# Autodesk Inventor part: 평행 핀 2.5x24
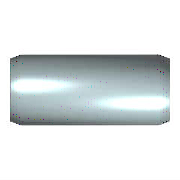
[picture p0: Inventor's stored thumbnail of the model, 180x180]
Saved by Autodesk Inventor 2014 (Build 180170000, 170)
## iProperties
Created: 2012-02
Part Number: 평행 핀 2.5x24
Material: 강철, 연강
Description: 평행 핀
Document SubType Name: Modeling
Standard: KS B 1320
Designer: mduedu
Standards Organization: KS
Language: ko-KR
Size Designation: B 2.5 x  24
Categories: <MemberInstance><Categories><Category DisplayName="조임쇠" InternalName="e4da775c-781d-43d5-af7c-5136215cf5a6" Mnemonic="FSTN"><Category DisplayName="핀" InternalNa
Density: 1 g/cm^3
Appearance: Yellow
IsCustomPart: 1
Author: mduedu
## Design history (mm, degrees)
sketch "스케치"
  geometry: C1 r 1.25 at (0, 0); 1 further point
  constraints: 1 centre point, 1 coincident
  dimensions: "d1" = 2.5 diameter of C1 (= NND)
extrude "본체" new body sketch "스케치" distance "d2" = 24 (= NLG); taper "d3" = 0 deg
chamfer "스케치2" distance "d8" = 0.4 (= PHH); stored, may be unused: angle "d9" = 15 deg (= FAWI), second distance "d12" = 0.4 (= PHH)
node "작업 평면1"
body "Solid1"
chamfer "모따기1" distance "d4" = 0.4 (= PHH); stored, may be unused: angle "d5" = 15 deg (= FAWI), second distance "d11" = 0.4 (= PHH)
other parameters: "NND" = 2.5 [user parameter; used in 1 equation term], "NLG" = 24 [user parameter; used in 1 equation term], "PHH" = 0.4 [user parameter; used in 4 equation terms], "FAWI" = 15 deg [user parameter; used in 2 equation terms], "d13" = 0, "d15" = 0, "d16" = 0, "KAH" = 0.3 [user parameter]
